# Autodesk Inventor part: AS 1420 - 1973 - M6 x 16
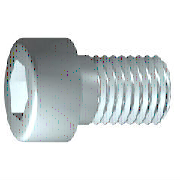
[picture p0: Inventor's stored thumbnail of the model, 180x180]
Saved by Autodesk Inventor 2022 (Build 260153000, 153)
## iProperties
Created: 2021-02
Part Number: AS 1420 - 1973 - M6 x 16
Material: Acciaio, Dolce
Description: Viti con esagono incassato metriche ISO
Document SubType Name: Modeling
Standard: AS 1420 - 1973
Designer: admin
Standards Organization: AS
Language: it-IT
Size Designation: M6 x 16
Categories: <MemberInstance><Categories><Category DisplayName="Elementi di fissaggio" InternalName="e4da775c-781d-43d5-af7c-5136215cf5a6" Mnemonic="FSTN"><Category DisplayN
Density: 7.85 g/cm^3
Appearance: Semilucidato
IsCustomPart: 0
Author: admin
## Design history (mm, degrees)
sketch "Schizzo1"
  geometry: L1 (-1.333, 0)-(16, 0); L2 (16, 0)-(16, 3); L3 (16, 3)-(2.5, 3); L4 (2.5, 3)-(1.886, 3); L5 (1.886, 3)-(0, 3); L6 (0, 3)-(0, 5); L7 (0, 5)-(-6, 5); L8 (-6, 5)-(-6, 2.887); L9 (-6, 2.887)-(-3, 2.887); L10 (-3, 2.887)-(-1.333, 0); L11 (-10.4, 0)-(20.4, 0) reference; L12 (0, -1)-(0, 6) reference; L13 (2.5, 3)-(0, 3)
  constraints: 22 end point, 6 parallel, 2 collinear, 2 perpendicular, 1 horizontal, 1 point on line
  dimensions: "d1" = 13.5 distance from line of L3.end L2 (= GEL); "d2" = 0.61355 distance of L4.end L3.end (computed from GAL); "d3" = 6 distance between parallel lines of L8 L6 (= KOH); "d4" = 3 distance of L8.end L9.end (= INTI); "d5" = 60 deg angle of L10 L1; "d6" = 6 diameter of L3 L1 (= GD); "d7" = 6 diameter of L5 L1 (= BDM); "d8" = 5.7735 diameter of L9 L1 (= 1.1547 x SW); "d9" = 10 diameter of L7 L1 (= KOD); "d26" = 16 distance between parallel lines of L12 L2 (= NLG)
revolve "Corpo" sketch "Schizzo1" stored, may be unused: angle "d10" = 90 deg
sketch "Schizzo2"
  geometry: L1 (0, -7)-(0, 7) reference; L2 (-7, 0)-(7, 0) reference; L3 (2.887, 0)-(1.443, -2.5); L4 (1.443, -2.5)-(-1.443, -2.5); L5 (-1.443, -2.5)-(-2.887, 0); L6 (-2.887, 0)-(-1.443, 2.5); L7 (-1.443, 2.5)-(1.443, 2.5); L8 (1.443, 2.5)-(2.887, 0); 2 further points
  constraints: 12 end point, 1 coincident, 1 horizontal alignment, 1 point on line, 12 other
extrude "Intaglio" join sketch "Schizzo2" stored distance "d11" = 10; taper "d12" = 0 deg
workplane "Work Plane1"
fillet "Fillet2" dims "d30" = 0.1 (= R)
body "Solid1"
fillet "Raccordo1" dims "d17" = 0.6 (= RR)
feature "Filettatura" dims "d13" = 13.5 (= GEL), "d14" = 0
chamfer "Smusso1" distance "d15" = 0.61345 (= -0.5 x SPD + 0.5 x GD); stored, may be unused: second distance "d16" = 0.61345 (= GUL), angle "d27" = 45 deg
other parameters: "GD" = 6 (= NND) [user parameter; used in 2 equation terms], "NLG" = 16 [user parameter; used in 1 equation term], "GEL" = 13.5 [user parameter; used in 2 equation terms], "KOD" = 10 [user parameter; used in 1 equation term], "KOH" = 6 (= NND) [user parameter; used in 1 equation term], "INTI" = 3 [user parameter; used in 1 equation term], "GAL" = 0.61345 (= 0.61345 x PTC) [user parameter; used in 1 equation term], "GUL" = 0.61345 (= 0.61345 x PTC) [user parameter; used in 1 equation term], "BDM" = 6 (= NND) [user parameter; used in 1 equation term], "SW" = 5 [user parameter; used in 2 equation terms], "RR" = 0.6 (= 0.1 x NND) [user parameter; used in 1 equation term], "SPD" = 4.7731 (= NND - 1.2269 x PTC) [user parameter; used in 1 equation term], "d19" = 0, "d28" = 0, "d29" = 0, "R" = 0.1 [user parameter; used in 1 equation term], "PHH" = 0.2 [user parameter], "GD1" = 4.7731 (= THREADDIA - 1.2269 x PTC) [user parameter], "THREADDIA" = 6 [user parameter; used in 1 equation term], "FAWI" = 45 deg [user parameter], "PTC" = 1 [user parameter; used in 5 equation terms], "KOH1" = 5.4 [user parameter], "NND" = 6 [user parameter; used in 5 equation terms], "TOA" = 30 deg [user parameter], "E0" = 5.775 (= 1.155 x SW) [user parameter]
